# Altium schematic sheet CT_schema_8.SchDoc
size 287 x 160 mm
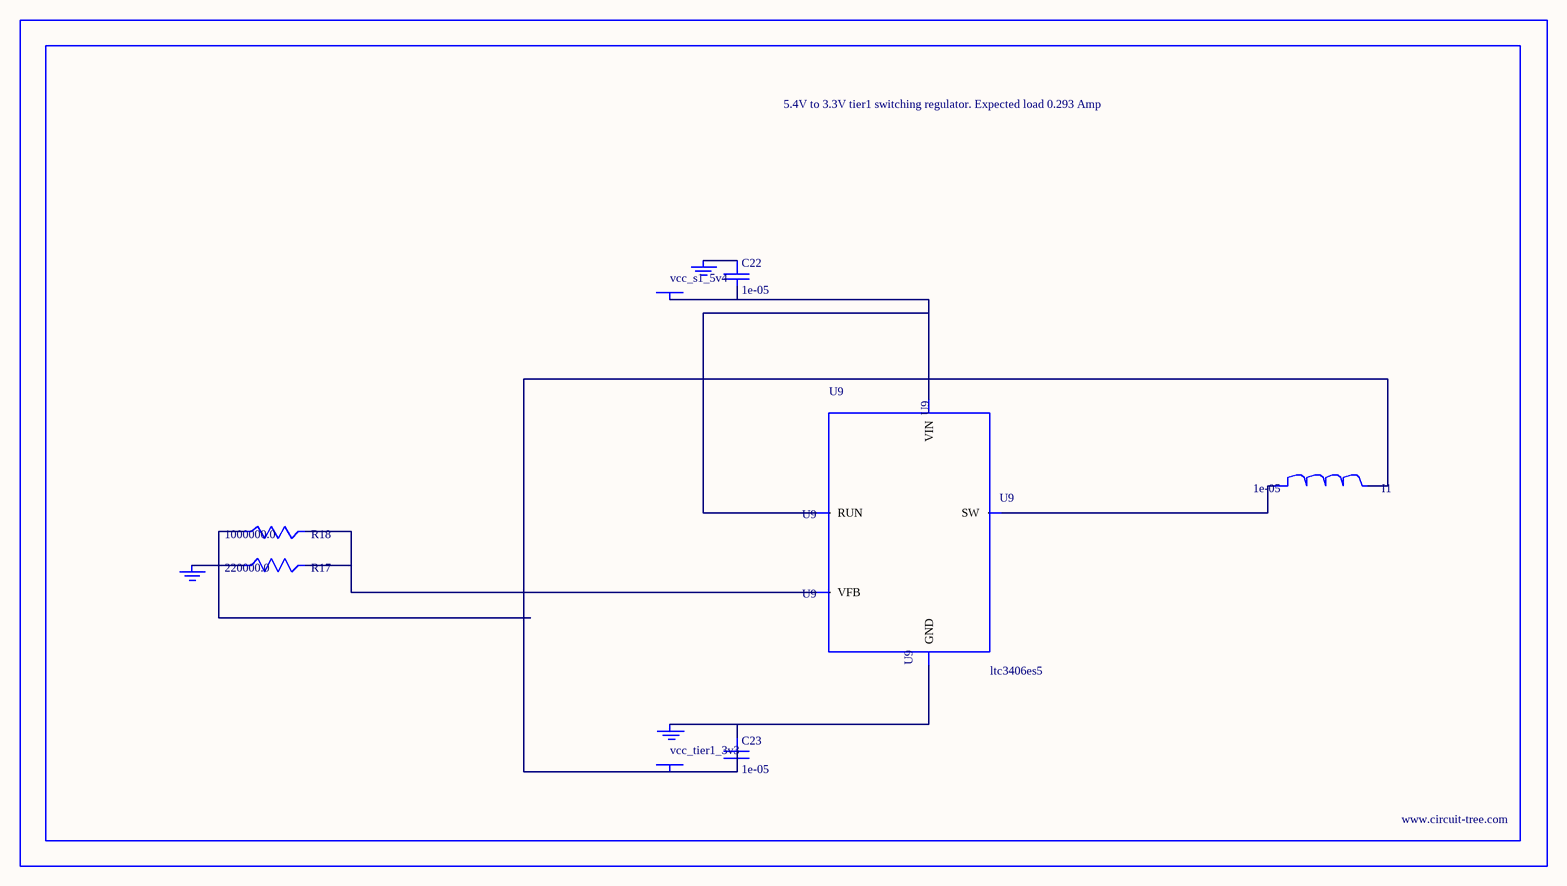
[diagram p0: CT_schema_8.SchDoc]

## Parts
BORDER7  (no value)
C22  1e-05  [C0805]
C23  1e-05  [C0805]
GND_INSTANCE_7_0  (no value)
GND_INSTANCE_7_1  (no value)
GND_INSTANCE_7_2  (no value)
I1  1e-05  [L0805]
POWER_INSTANCE_7_0  vcc_tier1_3v3
POWER_INSTANCE_7_1  vcc_s1_5v4
R17  220000.0  [R0603]
R18  1000000.0  [R0603]
U9  ltc3406es5  [TSOT-23-5]

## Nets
NetC22_1: C22.1 GND_INSTANCE_7_1.0(GND)
NetC22_2: C22.2 POWER_INSTANCE_7_1.0(PWR) U9.1(RUN) U9.4(VIN)
NetC23_1: C23.1 GND_INSTANCE_7_0.0(GND) U9.2(GND)
NetC23_2: C23.2 I1.2 POWER_INSTANCE_7_0.0(PWR) R18.1
NetGND_INSTANCE_7_2_0: GND_INSTANCE_7_2.0(GND) R17.1
NetI1_1: I1.1 U9.3(SW)
NetR17_2: R17.2 R18.2 U9.5(VFB)

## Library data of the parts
BORDER7 = BORDER_PAGE7
C22 C23 = C0805C106K8RACTU
GND_INSTANCE_7_0-GND_INSTANCE_7_2 = GND
I1 = L0805R100MDWST
POWER_INSTANCE_7_0 POWER_INSTANCE_7_1 = PWR
R17 = RC0603JR-07220KL
R18 = RC0603JR-071ML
